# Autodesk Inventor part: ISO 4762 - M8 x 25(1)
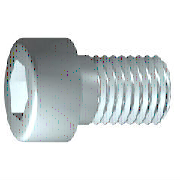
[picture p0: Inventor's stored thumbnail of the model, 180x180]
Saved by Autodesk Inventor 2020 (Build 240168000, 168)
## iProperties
Created: 2019-01
Part Number: ISO 4762 - M8 x 25(1)
Material: Nerezová ocel 440C
Description: Šroub s válcovou hlavou s vnitřním šestihranem
Document SubType Name: Modeling
Standard: ISO 4762
Designer: doma
Standard Revision: Fourth edition 2004-03-01
Standards Organization: ISO
Language: cs-CZ
Size Designation: M8 x 25
Categories: <MemberInstance><Categories><Category DisplayName="Spojovací materiál" InternalName="e4da775c-781d-43d5-af7c-5136215cf5a6" Mnemonic="FSTN"><Category DisplayName
Density: 7.75 g/cm^3
Appearance: Pololeštěná
IsCustomPart: 0
Author: doma
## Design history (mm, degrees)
sketch "Náčrt1"
  geometry: L1 (-2, 0)-(25, 0); L2 (25, 0)-(25, 4); L3 (25, 4)-(3.125, 4); L4 (3.125, 4)-(2.358, 4); L5 (2.358, 4)-(0, 4); L6 (0, 4)-(0, 6.5); L7 (0, 6.5)-(-8, 6.5); L8 (-8, 6.5)-(-8, 3.464); L9 (-8, 3.464)-(-4, 3.464); L10 (-4, 3.464)-(-2, 0); L11 (-14.6, 0)-(31.6, 0) reference; L12 (0, -1.3)-(0, 7.8) reference; L13 (3.125, 4)-(0, 4)
  constraints: 22 end point, 6 parallel, 2 collinear, 2 perpendicular, 1 horizontal, 1 point on line
  dimensions: "d1" = 21.875 distance from line of L3.end L2 (= GEL); "d2" = 0.76691 distance of L4.end L3.end (computed from GAL); "d3" = 8 distance between parallel lines of L8 L6 (= KOH); "d4" = 4 distance of L8.end L9.end (= INTI); "d5" = 60 deg angle of L10 L1; "d6" = 8 diameter of L3 L1 (= GD); "d7" = 8 diameter of L5 L1 (= BDM); "d8" = 6.9282 diameter of L9 L1 (= 1.1547 x SW); "d9" = 13 diameter of L7 L1 (= KOD); "d26" = 25 distance between parallel lines of L12 L2 (= NLG)
revolve "Těleso" sketch "Náčrt1" stored, may be unused: angle "d10" = 90 deg
sketch "Náčrt2"
  geometry: L1 (0, -9.1)-(0, 9.1) reference; L2 (-9.1, 0)-(9.1, 0) reference; L3 (3.464, 0)-(1.732, -3); L4 (1.732, -3)-(-1.732, -3); L5 (-1.732, -3)-(-3.464, 0); L6 (-3.464, 0)-(-1.732, 3); L7 (-1.732, 3)-(1.732, 3); L8 (1.732, 3)-(3.464, 0); 2 further points
  constraints: 12 end point, 1 coincident, 1 horizontal alignment, 1 point on line, 12 other
extrude "Drážka" join sketch "Náčrt2" stored distance "d11" = 10; taper "d12" = 0 deg
workplane "Work Plane1"
fillet "Fillet2" dims "d30" = 0.1 (= R)
body "Solid1"
fillet "Zaoblení1" dims "d17" = 0.8 (= RR)
feature "Závit" dims "d13" = 21.875 (= GEL), "d14" = 0
chamfer "Zkosení1" distance "d15" = 0.76681 (= -0.5 x SPD + 0.5 x GD); stored, may be unused: second distance "d16" = 0.76681 (= GUL), angle "d27" = 45 deg
other parameters: "GD" = 8 [user parameter; used in 2 equation terms], "NLG" = 25 [user parameter; used in 1 equation term], "GEL" = 21.875 [user parameter; used in 2 equation terms], "KOD" = 13 [user parameter; used in 1 equation term], "KOH" = 8 [user parameter; used in 1 equation term], "INTI" = 4 [user parameter; used in 1 equation term], "GAL" = 0.76681 (= 0.61345 x PTC) [user parameter; used in 1 equation term], "GUL" = 0.76681 (= 0.61345 x PTC) [user parameter; used in 1 equation term], "BDM" = 8 (= NND) [user parameter; used in 1 equation term], "SW" = 6 [user parameter; used in 2 equation terms], "RR" = 0.8 [user parameter; used in 1 equation term], "SPD" = 6.46637 (= NND - 1.2269 x PTC) [user parameter; used in 1 equation term], "d19" = 0, "d28" = 0, "d29" = 0, "R" = 0.1 [user parameter; used in 1 equation term], "TOA" = 30 deg [user parameter], "GD1" = 6.46637 (= THREADDIA - 1.2269 x PTC) [user parameter], "THREADDIA" = 8 [user parameter; used in 1 equation term], "FAWI" = 45 deg [user parameter], "TPU" = 8 (computed from PTC) [user parameter], "PTC" = 1.25 [user parameter; used in 5 equation terms], "NND" = 8 [user parameter; used in 2 equation terms], "E0" = 6.93 (= 1.155 x SW) [user parameter]
